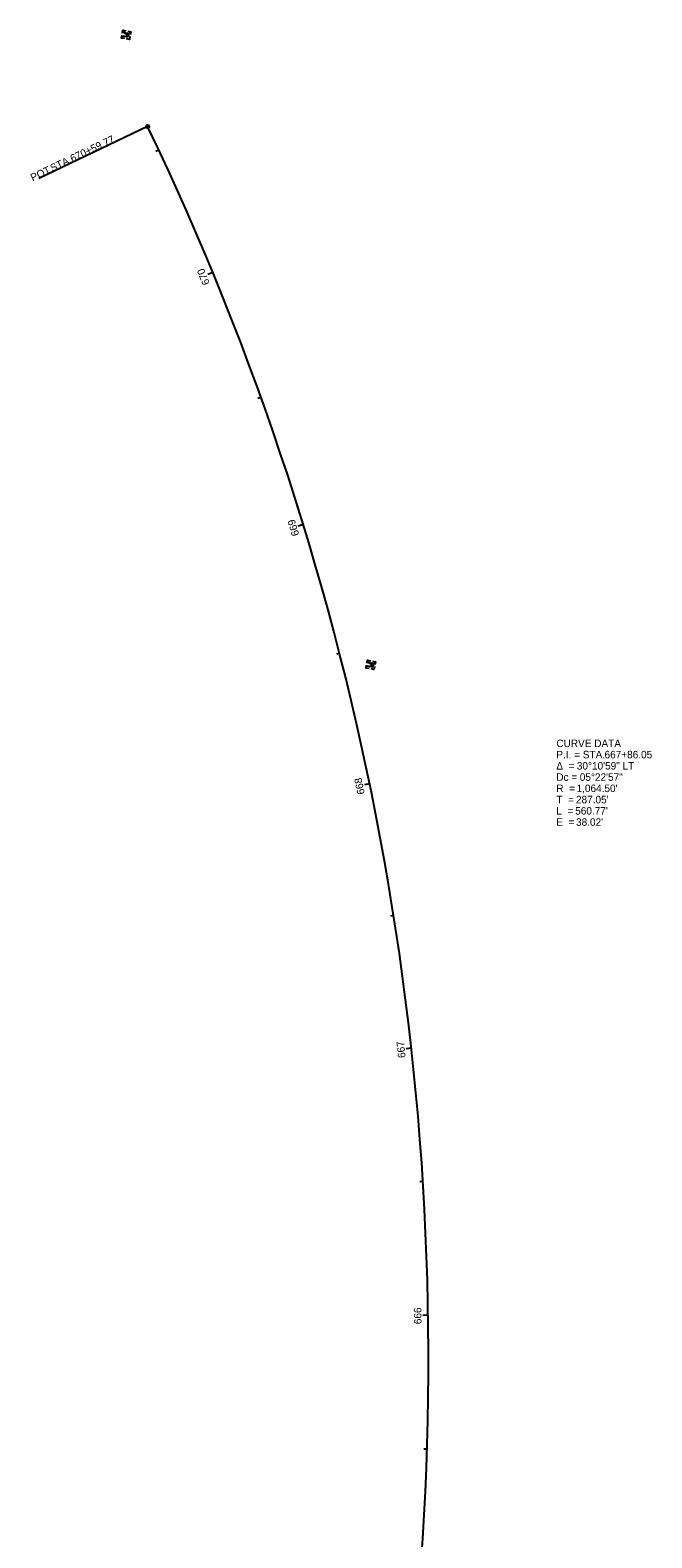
# Model space of a CAD drawing. Extents: x 171681 to 172332, y 456784 to 458794.
# Drawn here: x 172099 to 172331, y 458231 to 458794 of the extents above; entities that cross this region are included whole.
import ezdxf

# ---------------------------------------------------------------- set-up
doc = ezdxf.new("R2010")
doc.units = 0
for name, color, linetype in [('GE_X_Alignment', 7, 'Continuous'), ('GE_X_Alignment_100_Cardinal_Points', 7, 'Continuous'), ('GE_X_Alignment_100_Curve_Data', 7, 'Continuous'), ('GE_X_Alignment_100_Stations', 7, 'Continuous'), ('SV_X_Mon_Cells_Found', 7, 'Continuous')]:
    doc.layers.add(name, color=color, linetype=linetype)

msp = doc.modelspace()

# ---------------------------------------------------------------- linework, layer by layer
at = {"layer": 'GE_X_Alignment'}
msp.add_arc((171183.53, 458297.29), 1064.5, 355.45598, 25.63893, dxfattribs=at)
msp.add_arc((171183.53, 458297.29), 1064.5, 355.45598, 25.63893, dxfattribs=at)
at = {"layer": 'GE_X_Alignment_100_Cardinal_Points'}
msp.add_line((172143.21, 458757.9), (172102.64, 458738.42), dxfattribs=at)
msp.add_circle((172143.21, 458757.9), 0.6, dxfattribs=at)
at = {"layer": 'GE_X_Alignment_100_Stations'}
for p, q in [((172147.4, 458749.07), (172146.31, 458748.56)), ((172167.55, 458703.32), (172165.7, 458702.55)), ((172185.53, 458656.67), (172184.4, 458656.26)), ((172201.3, 458609.22), (172199.38, 458608.64)), ((172214.82, 458561.09), (172213.66, 458560.79)), ((172226.07, 458512.38), (172224.11, 458511.97)), ((172235.02, 458463.19), (172233.83, 458463)), ((172241.65, 458413.64), (172239.66, 458413.42)), ((172245.94, 458363.83), (172244.75, 458363.75)), ((172247.9, 458313.87), (172245.9, 458313.84)), ((172247.5, 458263.87), (172246.3, 458263.91))]:
    msp.add_line(p, q, dxfattribs=at)
at = {"layer": 'SV_X_Mon_Cells_Found'}
for p, q in [((172135.2, 458792.1), (172135.2, 458792.1)), ((172226.5, 458556.8), (172226.5, 458556.8))]:
    msp.add_line(p, q, dxfattribs=at)
for points in [[(172134.55, 458790.7), (172133.44, 458790.91), (172133.65, 458792.01)], [(172133.79, 458792.73), (172134.01, 458793.86), (172135.11, 458793.65)], [(172136.04, 458791.19), (172134.08, 458791.56), (172136.18, 458791.91), (172134.36, 458793.01), (172136.32, 458792.64)], [(172136.6, 458791.45), (172136.39, 458790.34), (172135.29, 458790.56)], [(172135.85, 458793.5), (172136.96, 458793.29), (172136.74, 458792.17)], [(172225.85, 458555.4), (172224.74, 458555.61), (172224.95, 458556.71)], [(172225.09, 458557.43), (172225.31, 458558.56), (172226.41, 458558.35)], [(172227.34, 458555.89), (172225.38, 458556.26), (172227.48, 458556.61), (172225.66, 458557.71), (172227.62, 458557.34)], [(172227.9, 458556.15), (172227.69, 458555.04), (172226.59, 458555.26)], [(172227.15, 458558.2), (172228.26, 458557.99), (172228.04, 458556.87)]]:
    msp.add_lwpolyline(points, dxfattribs=at)

# ---------------------------------------------------------------- texts
at = {"layer": 'GE_X_Alignment_100_Cardinal_Points'}
for s, p in [('670+59.77', (172115.14, 458744.46)), (' STA. ', (172106.73, 458740.43)), ('POT', (172100.31, 458737.34))]:
    msp.add_text(s, height=2.8, rotation=25.6389, dxfattribs=at).set_placement(p)
at = {"layer": 'GE_X_Alignment_100_Curve_Data'}
for s, p in [('CURVE DATA', (172295.75, 458526.09)), ('Δ  = ', (172295.75, 458517.69)), ('P.I. = STA. ', (172295.75, 458521.89)), ('30°10\'59" LT', (172303.4, 458517.69)), ('667+86.05', (172313.74, 458521.89)), ('Dc = ', (172295.75, 458513.49)), ('05°22\'57"', (172304.5, 458513.49)), ('R  = ', (172295.75, 458509.29)), ("1,064.50'", (172303.29, 458509.29)), ('T  = ', (172295.75, 458505.09)), ('L  = ', (172295.75, 458500.89)), ("560.77'", (172302.79, 458500.89)), ("287.05'", (172303.07, 458505.09)), ('E  = ', (172295.75, 458496.69)), ("38.02'", (172303.1, 458496.69))]:
    msp.add_text(s, height=2.8, dxfattribs=at).set_placement(p)
at = {"layer": 'GE_X_Alignment_100_Stations'}
for s, rotation, p in [('670', 112.4221, (172166.48, 458699.34)), ('669', 107.0397, (172199.85, 458605.41)), ('668', 101.6573, (172224.28, 458508.69)), ('667', 96.2748, (172239.52, 458410.14)), ('666', 90.8924, (172245.45, 458310.57))]:
    msp.add_text(s, height=2.8, rotation=rotation, dxfattribs=at).set_placement(p)

doc.saveas('drawing.dxf')
